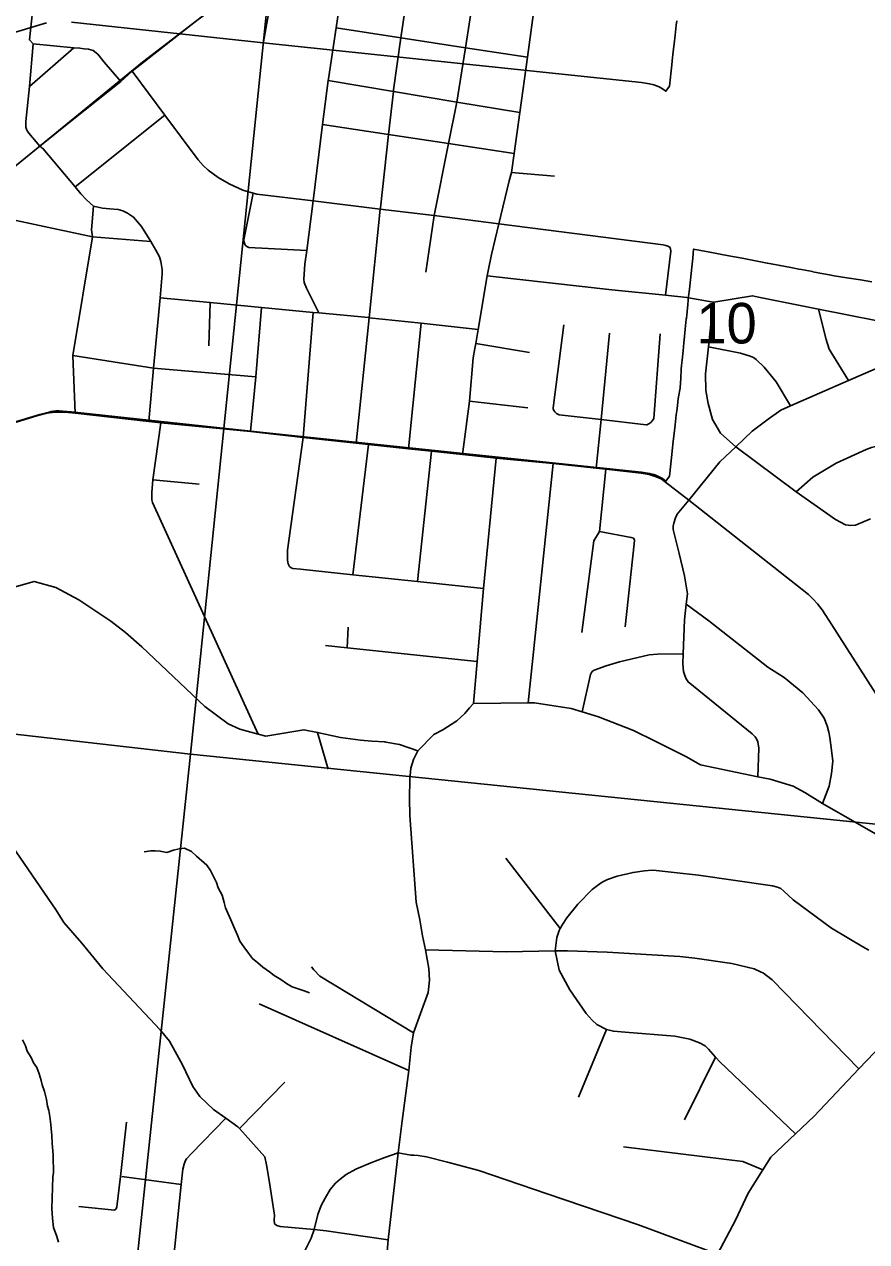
# Model space of a CAD drawing. Extents: x -8.2 to 38.5, y -0.1 to 21.9.
# Drawn here: x 7.706 to 8.576, y 17.376 to 18.635 of the extents above; entities that cross this region are included whole.
import ezdxf

# ---------------------------------------------------------------- set-up
doc = ezdxf.new("R2010")
doc.units = 0
for name, color, linetype in [('Default', 7, 'Continuous'), ('GM_X_Adjacent_County_Text', 7, 'Continuous'), ('GM_X_Airport_Location_Class_3', 7, 'Continuous'), ('GM_X_County_Road_Text', 7, 'Continuous'), ('GM_X_Minor_River', 7, 'Continuous'), ('GM_X_Section_Text', 7, 'Continuous'), ('GM_X_Township_Subdivision_Text', 7, 'Continuous'), ('GM_X_Township_Text', 7, 'Continuous'), ('GM_X_US_Location', 7, 'Continuous')]:
    doc.layers.add(name, color=color, linetype=linetype)

msp = doc.modelspace()

# ---------------------------------------------------------------- linework, layer by layer
at = {"layer": 'Default'}
msp.add_lwpolyline([(8.9634, 18.556), (8.9634, 18.7145), (7.9789, 18.8702), (7.8777, 17.8803), (8.8823, 17.7777)], close=True, dxfattribs=at)
for points in [[(7.7289, 18.6361), (7.722, 18.6342), (7.629, 18.6062), (7.6, 18.5978), (7.5969, 18.5969), (7.5925, 18.5959), (7.5878, 18.5953), (7.5775, 18.5947), (7.5814, 18.6069), (7.6487, 18.8063)], [(8.3802, 18.6382), (8.3797, 18.6339), (8.3786, 18.6236), (8.3775, 18.6145), (8.3762, 18.6038), (8.3762, 18.603), (8.3758, 18.6002), (8.375, 18.5929), (8.3725, 18.5707), (8.369, 18.5654), (8.3653, 18.568), (8.3618, 18.5699), (8.3591, 18.5711), (8.3563, 18.5721), (8.3521, 18.5733), (8.3477, 18.5739), (8.3436, 18.5744), (7.9594, 18.6149), (7.7548, 18.6369)]]:
    msp.add_lwpolyline(points, dxfattribs=at)
at = {"layer": 'GM_X_Adjacent_County_Text'}
for points in [[(6.9585, 18.9896), (7.9789, 18.8702), (7.8777, 17.8803), (6.8589, 17.9964)], [(6.8589, 17.9964), (7.8777, 17.8803), (7.7722, 16.8835), (6.7536, 16.9855)], [(7.8777, 17.8803), (8.8823, 17.7777), (8.7794, 16.8117), (7.7722, 16.8835)]]:
    msp.add_lwpolyline(points, close=True, dxfattribs=at)
at = {"layer": 'GM_X_Airport_Location_Class_3'}
msp.add_lwpolyline([(8.4223, 17.3635), (8.441, 17.3986), (8.4539, 17.4264), (8.4691, 17.4508), (8.4773, 17.4639), (8.5028, 17.4879), (8.522, 17.506), (8.5683, 17.5551), (8.5844, 17.5721), (8.6351, 17.6259), (8.6429, 17.6341), (8.7111, 17.7045), (8.7547, 17.7501), (8.8431, 17.8388), (8.8435, 17.8393), (8.8783, 17.8753), (8.8884, 17.8837), (8.8984, 17.8911)], dxfattribs=at)
at = {"layer": 'GM_X_Minor_River'}
for points in [[(7.8299, 17.7794), (7.8368, 17.7803), (7.8413, 17.7805), (7.8462, 17.7799), (7.8534, 17.7788), (7.8603, 17.7812), (7.8661, 17.7825), (7.8714, 17.783), (7.8789, 17.7797), (7.884, 17.7749), (7.8947, 17.7657), (7.8983, 17.7599), (7.9015, 17.754), (7.9046, 17.7478), (7.9063, 17.742), (7.9106, 17.7346), (7.9126, 17.727), (7.9139, 17.7216), (7.9195, 17.7092), (7.9236, 17.6995), (7.9264, 17.6933), (7.9288, 17.6871), (7.9328, 17.6813), (7.9375, 17.6746), (7.9418, 17.6691), (7.9473, 17.6647), (7.9525, 17.6603), (7.9595, 17.6554), (7.9643, 17.6514), (7.971, 17.6474), (7.9769, 17.6433), (7.9828, 17.64), (7.9888, 17.6379), (7.9952, 17.6357), (8.0005, 17.6336)], [(7.704, 17.585), (7.7072, 17.5788), (7.709, 17.5734), (7.713, 17.5668), (7.7155, 17.5614), (7.7188, 17.5564), (7.7213, 17.5498), (7.7234, 17.5429), (7.7244, 17.5387), (7.7269, 17.5318), (7.7289, 17.5234), (7.7299, 17.5165), (7.7313, 17.5119), (7.7322, 17.5057), (7.7335, 17.4977), (7.7338, 17.4935), (7.7344, 17.4863), (7.7349, 17.4779), (7.7354, 17.4702), (7.7357, 17.466), (7.7359, 17.4592), (7.7361, 17.4531), (7.736, 17.4481), (7.7355, 17.4436), (7.7346, 17.4105), (7.7348, 17.4059), (7.7351, 17.4009), (7.7363, 17.391), (7.7395, 17.3818), (7.7413, 17.376)]]:
    msp.add_lwpolyline(points, dxfattribs=at)
at = {"layer": 'GM_X_Section_Text'}
msp.add_lwpolyline([(8.5816, 18.3685), (8.5701, 18.3704), (8.5558, 18.3727), (8.5428, 18.3748), (8.5378, 18.3756), (8.5316, 18.3768), (8.5206, 18.3789), (8.5204, 18.379), (8.5092, 18.3811), (8.5064, 18.3816), (8.4999, 18.3829), (8.4981, 18.3832), (8.4869, 18.3853), (8.4739, 18.3878), (8.4737, 18.3879), (8.4599, 18.3905), (8.4478, 18.3928), (8.4339, 18.3955), (8.4144, 18.3992), (8.4051, 18.4009), (8.3976, 18.4024), (8.3966, 18.393), (8.3956, 18.3836), (8.3932, 18.361), (8.3924, 18.3534), (8.3916, 18.3452), (8.3904, 18.3339), (8.3901, 18.3309), (8.39, 18.3298), (8.389, 18.3197), (8.3878, 18.3085), (8.3875, 18.3056), (8.3866, 18.2971), (8.3856, 18.2876), (8.3851, 18.2821), (8.3848, 18.2782), (8.3842, 18.2686), (8.3836, 18.2593), (8.3835, 18.2586), (8.3821, 18.2498), (8.3813, 18.2447), (8.3808, 18.2404), (8.3802, 18.2353), (8.3797, 18.231), (8.3786, 18.2208), (8.3775, 18.2116), (8.3762, 18.2009), (8.3762, 18.2001), (8.3758, 18.1973), (8.375, 18.19), (8.3725, 18.1678), (8.369, 18.1625), (8.3653, 18.1651), (8.3618, 18.1671), (8.3591, 18.1683), (8.3563, 18.1693), (8.3521, 18.1704), (8.3477, 18.1711), (8.3436, 18.1716), (7.9594, 18.212), (7.7548, 18.234), (7.7458, 18.2349), (7.7421, 18.2351), (7.7404, 18.2351), (7.7385, 18.235), (7.736, 18.2347), (7.7339, 18.2344), (7.7316, 18.2338), (7.7289, 18.2332), (7.722, 18.2313), (7.629, 18.2033)], dxfattribs=at)
at = {"layer": 'GM_X_Township_Subdivision_Text'}
for p, q in [((7.953, 18.6164), (7.9662, 18.691)), ((7.7112, 18.5703), (7.7571, 18.6103)), ((7.7585, 18.4666), (7.8512, 18.5409)), ((8.2094, 18.4816), (8.2539, 18.4776)), ((8.121, 18.3785), (8.1294, 18.4369)), ((7.8966, 18.3022), (7.8982, 18.347)), ((7.9942, 18.2076), (8.0045, 18.3369)), ((8.103, 18.1959), (8.1159, 18.3257)), ((8.1725, 18.3049), (8.228, 18.2953)), ((8.166, 18.2452), (8.2261, 18.2383)), ((8.0455, 18.0658), (8.0616, 18.2005)), ((8.1121, 18.0587), (8.1268, 18.1935)), ((8.2267, 17.9333), (8.2526, 18.1806)), ((7.8388, 18.1639), (7.8868, 18.1594)), ((8.0396, 17.9903), (8.0405, 18.0115)), ((8.0201, 17.8648), (8.0091, 17.9027)), ((8.2598, 17.7001), (8.2036, 17.7729)), ((7.9486, 17.6221), (8.1033, 17.5533)), ((8.2785, 17.5259), (8.3074, 17.5956)), ((8.3882, 17.5025), (8.4202, 17.567)), ((7.9283, 17.4934), (7.9752, 17.5412)), ((7.8068, 17.4437), (7.8682, 17.4355))]:
    msp.add_line(p, q, dxfattribs=at)
for points in [[(8.0104, 18.3364), (7.9976, 18.3618), (7.9953, 18.3678), (7.9948, 18.3714), (7.996, 18.3866), (7.9978, 18.401), (8.0043, 18.4521), (8.0142, 18.531), (8.02, 18.5765), (8.0202, 18.5784), (8.0281, 18.6309), (8.0367, 18.6901), (8.0452, 18.7465), (8.054, 18.8028), (8.0623, 18.859), (8.0642, 18.8692), (8.0663, 18.8751), (8.0706, 18.8809), (8.102, 18.91)], [(8.0489, 18.2017), (8.0624, 18.3314), (8.0737, 18.4436), (8.0739, 18.4449), (8.0823, 18.5207), (8.0873, 18.5653), (8.0874, 18.567), (8.0952, 18.6207), (8.1036, 18.6788), (8.1119, 18.7365), (8.1197, 18.7914), (8.1284, 18.8486)], [(8.1294, 18.4369), (8.1443, 18.5113), (8.1529, 18.5543), (8.1617, 18.6105), (8.1707, 18.6686), (8.1795, 18.7252), (8.188, 18.7796), (8.1923, 18.8072), (8.1942, 18.8382)], [(8.1589, 18.19), (8.166, 18.2452), (8.1698, 18.2901), (8.1716, 18.2995), (8.1725, 18.3049), (8.1749, 18.3193), (8.1843, 18.3748), (8.1852, 18.3798), (8.1887, 18.3968), (8.1963, 18.4284), (8.2071, 18.4728), (8.2094, 18.4816), (8.212, 18.5011), (8.2179, 18.5435), (8.2259, 18.6006), (8.234, 18.6591), (8.2342, 18.6607), (8.242, 18.7148), (8.2497, 18.769), (8.2576, 18.8235)], [(7.7222, 18.5086), (7.7107, 18.522), (7.7085, 18.5251), (7.7077, 18.5284), (7.7076, 18.5318), (7.7077, 18.5341), (7.7112, 18.5703), (7.7153, 18.6144), (7.7113, 18.6186), (7.7146, 18.6474), (7.7191, 18.6732)], [(8.0281, 18.6309), (8.0952, 18.6207), (8.1617, 18.6105), (8.2259, 18.6006)], [(7.7153, 18.6144), (7.7571, 18.6103), (7.7632, 18.61), (7.7677, 18.6094), (7.7723, 18.6088), (7.7771, 18.6075), (7.782, 18.6037), (7.7886, 18.5954), (7.8057, 18.5756)], [(7.8176, 18.5863), (7.8512, 18.5409), (7.8855, 18.4946), (7.8907, 18.4887), (7.8961, 18.4838), (7.9063, 18.4762), (7.9175, 18.4698), (7.9317, 18.4633), (7.9423, 18.4602), (7.9464, 18.4591), (8.0043, 18.4521), (8.0737, 18.4436), (8.1294, 18.4369), (8.1963, 18.4284), (8.3661, 18.4067), (8.3689, 18.4062), (8.371, 18.4055)], [(8.02, 18.5765), (8.0873, 18.5653), (8.1529, 18.5543), (8.2179, 18.5435)], [(8.0142, 18.531), (8.0823, 18.5207), (8.1443, 18.5113), (8.1555, 18.5096)], [(7.8345, 18.2242), (7.8396, 18.2791), (7.8464, 18.3519), (7.8486, 18.3766), (7.8485, 18.3811), (7.8476, 18.3854), (7.8469, 18.3895), (7.8456, 18.3942), (7.8437, 18.3981), (7.842, 18.4011), (7.8366, 18.4102), (7.8271, 18.4256), (7.8189, 18.4355), (7.8125, 18.4396), (7.8079, 18.442), (7.8031, 18.4434), (7.7944, 18.4439), (7.7868, 18.4445), (7.7774, 18.4468), (7.7702, 18.4531), (7.7644, 18.4593), (7.7585, 18.4666), (7.7256, 18.506), (7.7222, 18.5086)], [(8.1555, 18.5096), (8.16, 18.509), (8.212, 18.5011)], [(7.9343, 18.4065), (7.9333, 18.4094), (7.9329, 18.4111), (7.9329, 18.412), (7.9423, 18.4602)], [(7.7587, 18.2326), (7.7562, 18.2924), (7.7763, 18.4151), (7.7753, 18.4223), (7.7774, 18.4468)], [(7.6619, 18.4396), (7.7763, 18.4151), (7.8366, 18.4102)], [(7.9343, 18.4065), (7.9358, 18.4051), (7.9367, 18.4045), (7.9381, 18.4041), (7.9978, 18.401)], [(8.3684, 18.3546), (8.3739, 18.4003), (8.3738, 18.4026), (8.3735, 18.4033), (8.3729, 18.4042), (8.371, 18.4055)], [(8.1843, 18.3748), (8.3129, 18.3603), (8.3684, 18.3546), (8.3905, 18.3523)], [(7.8464, 18.3519), (7.8982, 18.347), (7.9512, 18.342), (8.0045, 18.3369), (8.0104, 18.3364), (8.0617, 18.3315), (8.0624, 18.3314), (8.1159, 18.3257), (8.1749, 18.3193)], [(8.3905, 18.3523), (8.4176, 18.3476), (8.4185, 18.3474), (8.4585, 18.3541), (8.4645, 18.3528), (8.5267, 18.3403), (8.6171, 18.3222), (8.6193, 18.3215), (8.6209, 18.3206), (8.6218, 18.3191), (8.6227, 18.316), (8.6249, 18.2957), (8.6207, 18.2723)], [(8.5802, 18.1236), (8.5649, 18.1171), (8.5601, 18.1165), (8.5546, 18.1174), (8.5441, 18.123), (8.5034, 18.1513), (8.4412, 18.198), (8.4252, 18.2122), (8.4171, 18.2261), (8.4126, 18.2429), (8.4102, 18.2563), (8.4099, 18.2734), (8.4128, 18.3012), (8.4176, 18.3476)], [(7.9396, 18.2137), (7.9453, 18.2704), (7.9512, 18.342)], [(8.5577, 18.2664), (8.5376, 18.2989), (8.5345, 18.3089), (8.5267, 18.3403)], [(8.254, 18.2341), (8.253, 18.2354), (8.2523, 18.2374), (8.2523, 18.2382), (8.2633, 18.324)], [(8.297, 18.1759), (8.3019, 18.2262), (8.3105, 18.3155)], [(8.3532, 18.223), (8.3552, 18.2252), (8.3563, 18.2274), (8.3629, 18.3148)], [(8.4128, 18.3012), (8.4461, 18.2946), (8.4559, 18.2917), (8.4595, 18.2902), (8.4622, 18.2882), (8.4704, 18.2804), (8.483, 18.2652), (8.4978, 18.2403)], [(7.7562, 18.2924), (7.8396, 18.2791), (7.9453, 18.2704)], [(8.464, 17.857), (8.465, 17.8866), (8.464, 17.8931), (8.4627, 17.8961), (8.4612, 17.8983), (8.4581, 17.9012), (8.3918, 17.9549), (8.3897, 17.9581), (8.3885, 17.9615), (8.3872, 17.9658), (8.3865, 17.9737), (8.3869, 17.9839), (8.388, 18.0193), (8.39, 18.0352), (8.3913, 18.0459), (8.3883, 18.0646), (8.3828, 18.0876), (8.3765, 18.1125), (8.3765, 18.1159), (8.377, 18.1189), (8.3788, 18.1244), (8.3807, 18.1283), (8.3925, 18.143), (8.4248, 18.1825), (8.4412, 18.198), (8.4582, 18.214), (8.4745, 18.2266), (8.4876, 18.2358), (8.4978, 18.2403), (8.5577, 18.2664), (8.5854, 18.2784)], [(8.254, 18.2341), (8.2559, 18.2323), (8.2578, 18.2313), (8.2586, 18.2311), (8.3019, 18.2262), (8.3484, 18.2208), (8.3493, 18.2208), (8.3513, 18.2216), (8.3532, 18.223)], [(7.9475, 17.9011), (7.8386, 18.1404), (7.8379, 18.1431), (7.8376, 18.146), (7.8376, 18.1469), (7.8377, 18.1507), (7.8388, 18.1639), (7.847, 18.2226)], [(7.9787, 18.0769), (7.9781, 18.0807), (7.9778, 18.0849), (7.9778, 18.091), (7.9942, 18.2076)], [(8.5034, 18.1513), (8.5209, 18.1665), (8.5448, 18.1812), (8.5759, 18.1951), (8.5812, 18.1971), (8.5899, 18.1992), (8.5968, 18.1997), (8.6097, 18.1987), (8.6199, 18.1961), (8.6263, 18.1929), (8.6297, 18.1897), (8.6329, 18.1856), (8.6366, 18.179), (8.6403, 18.1681), (8.6458, 18.1521)], [(8.2822, 18.0062), (8.2946, 18.1007), (8.3002, 18.1105), (8.3067, 18.1749)], [(8.3267, 18.012), (8.3363, 18.0978), (8.3364, 18.1016), (8.336, 18.1026), (8.3353, 18.1035), (8.333, 18.1043), (8.3002, 18.1105)], [(7.9787, 18.0769), (7.9801, 18.0744), (7.9817, 18.073), (7.9835, 18.0723), (7.9915, 18.0715), (8.0455, 18.0658), (8.1121, 18.0587), (8.1804, 18.0515)], [(8.5308, 17.8293), (8.5377, 17.8472), (8.54, 17.8602), (8.5413, 17.873), (8.5402, 17.8843), (8.5383, 17.8976), (8.5373, 17.903), (8.5356, 17.9097), (8.5323, 17.9174), (8.5266, 17.9262), (8.5103, 17.9437), (8.491, 17.9594), (8.4741, 17.9701), (8.4134, 18.018), (8.39, 18.0352)], [(8.0173, 17.9927), (8.0396, 17.9903), (8.1738, 17.976)], [(8.2825, 17.9242), (8.291, 17.9626), (8.2922, 17.9648), (8.2929, 17.9658), (8.2938, 17.9664), (8.2949, 17.9671), (8.3072, 17.9717), (8.3209, 17.9756), (8.3518, 17.9829), (8.3602, 17.9838), (8.3869, 17.9839)], [(7.6807, 17.8035), (7.7389, 17.7192), (7.7468, 17.7063), (7.7654, 17.6848), (7.7872, 17.6586), (7.8465, 17.5955), (7.8561, 17.5835), (7.8696, 17.5592), (7.8801, 17.5369), (7.885, 17.53), (7.8875, 17.5265), (7.9016, 17.5129), (7.9142, 17.504), (7.9267, 17.4952), (7.9283, 17.4934), (7.9545, 17.4641), (7.9562, 17.4557), (7.9589, 17.4397), (7.9644, 17.4039), (7.964, 17.3988), (7.9645, 17.395), (7.9668, 17.393), (7.9703, 17.3922), (8.0056, 17.3891), (8.0178, 17.3876), (8.082, 17.3784)], [(8.2546, 17.6769), (8.2564, 17.6907), (8.2588, 17.6982), (8.2598, 17.7001), (8.262, 17.7043), (8.2666, 17.7113), (8.2781, 17.7252), (8.2929, 17.7405), (8.2981, 17.7447), (8.3029, 17.7479), (8.3087, 17.7506), (8.3187, 17.7543), (8.3351, 17.7581), (8.3468, 17.7598), (8.3549, 17.7604), (8.3588, 17.7602), (8.3773, 17.7579), (8.4027, 17.7551), (8.4792, 17.7442), (8.4841, 17.743), (8.4876, 17.7415), (8.4908, 17.7386), (8.5005, 17.7297), (8.5401, 17.7006), (8.5724, 17.6812), (8.5787, 17.6777)], [(8.1207, 17.6779), (8.204, 17.676), (8.2546, 17.6769), (8.2671, 17.6772), (8.3081, 17.6755), (8.3833, 17.6711), (8.3987, 17.6696), (8.4371, 17.6638), (8.4601, 17.6583), (8.4667, 17.6554), (8.4697, 17.6539), (8.4727, 17.6517), (8.4788, 17.6469), (8.5683, 17.5551)], [(8.2546, 17.6769), (8.2587, 17.6572), (8.2696, 17.6368), (8.2865, 17.6121), (8.2927, 17.6055), (8.2976, 17.601), (8.3074, 17.5956), (8.3147, 17.5939), (8.3268, 17.5929), (8.378, 17.5887), (8.3935, 17.5857), (8.4037, 17.582), (8.4094, 17.5787), (8.4129, 17.5753), (8.4202, 17.567), (8.4245, 17.5622), (8.5028, 17.4879)], [(8.0026, 17.6604), (8.0052, 17.6573), (8.0115, 17.6507), (8.1082, 17.5923)], [(7.8449, 17.2096), (7.8682, 17.4355), (7.8698, 17.4515), (7.871, 17.4566), (7.8723, 17.4598), (7.8736, 17.4621), (7.8786, 17.4677), (7.9142, 17.504)], [(7.7624, 17.4128), (7.7991, 17.409), (7.8008, 17.4104), (7.8015, 17.4126), (7.8053, 17.4439), (7.8115, 17.5001)], [(8.0464, 17.1047), (8.0579, 17.1826), (8.0808, 17.3663), (8.082, 17.3784), (8.0923, 17.4683)], [(8.0923, 17.4683), (8.1053, 17.4659), (8.1085, 17.4658), (8.1131, 17.4654), (8.1216, 17.464), (8.1432, 17.4586), (8.1756, 17.4499), (8.2461, 17.426), (8.3407, 17.3939), (8.4223, 17.3635)], [(8.3252, 17.4743), (8.4484, 17.4593), (8.4691, 17.4508)]]:
    msp.add_lwpolyline(points, dxfattribs=at)
at = {"layer": 'GM_X_Township_Text'}
for points in [[(7.6449, 18.3925), (7.648, 18.4019), (7.6619, 18.4396), (7.6681, 18.4532), (7.6732, 18.4626), (7.6781, 18.4697), (7.6873, 18.4796), (7.6962, 18.4876), (7.7222, 18.5086), (7.7572, 18.5369), (7.8057, 18.5756), (7.8176, 18.5863), (7.883, 18.6375), (7.9302, 18.6726), (7.9515, 18.6883), (7.9521, 18.689)], [(7.5965, 18.1925), (7.7201, 18.2303), (7.7293, 18.2328), (7.7376, 18.2338), (7.7478, 18.2339), (7.7587, 18.2326), (7.8345, 18.2242), (7.847, 18.2226), (7.9396, 18.2137), (7.9942, 18.2076), (8.0489, 18.2017), (8.0616, 18.2005), (8.103, 18.1959), (8.1268, 18.1935), (8.1589, 18.19), (8.1936, 18.1864), (8.2526, 18.1806), (8.297, 18.1759), (8.3067, 18.1749), (8.3434, 18.1709), (8.3516, 18.1695), (8.358, 18.1673), (8.3639, 18.1649), (8.3925, 18.143)], [(8.17, 17.9328), (8.1738, 17.976), (8.1804, 18.0515), (8.1936, 18.1864)], [(8.3925, 18.143), (8.5161, 18.0452), (8.5212, 18.0404), (8.5255, 18.0356), (8.5303, 18.0294), (8.5342, 18.0235), (8.5405, 18.0141), (8.6046, 17.9138), (8.6082, 17.9079), (8.61, 17.904), (8.611, 17.9), (8.6118, 17.8926), (8.6072, 17.7856)], [(7.6955, 18.0529), (7.7161, 18.0588), (7.7386, 18.0525), (7.7622, 18.0397), (7.7953, 18.0179), (7.8106, 18.006), (7.8274, 17.9912), (7.8924, 17.9296), (7.9167, 17.9116), (7.9287, 17.906), (7.9475, 17.9011), (7.9555, 17.899), (7.9949, 17.9056), (8.0091, 17.9027), (8.0326, 17.8976), (8.0535, 17.8948), (8.065, 17.8938), (8.0786, 17.8929)], [(8.0786, 17.8929), (8.0794, 17.8928), (8.0938, 17.8904), (8.1125, 17.8839), (8.1291, 17.9006), (8.1386, 17.9054), (8.1529, 17.9149), (8.1613, 17.9222), (8.1661, 17.9281), (8.17, 17.9328)], [(8.17, 17.9328), (8.2267, 17.9333), (8.233, 17.9334), (8.2712, 17.9276), (8.2825, 17.9242), (8.2992, 17.919), (8.3353, 17.9049), (8.3578, 17.8938), (8.3894, 17.8779), (8.4048, 17.8692), (8.464, 17.857), (8.4766, 17.8544), (8.5003, 17.8474), (8.5124, 17.8407), (8.5308, 17.8293), (8.6072, 17.7856)], [(8.0923, 17.4683), (8.0964, 17.5013), (8.1033, 17.5533), (8.1058, 17.5776), (8.1082, 17.5923), (8.1155, 17.6122), (8.1233, 17.634), (8.1245, 17.6467), (8.124, 17.6588), (8.1207, 17.6779), (8.1176, 17.6925), (8.1146, 17.7092), (8.1109, 17.7275), (8.1043, 17.8168), (8.1039, 17.8344), (8.1044, 17.8545), (8.1055, 17.8657), (8.108, 17.8748), (8.1125, 17.8839)], [(7.995, 17.3655), (8.0023, 17.3799), (8.0056, 17.3891), (8.0094, 17.4045), (8.0127, 17.4139), (8.0168, 17.4214), (8.0221, 17.4303), (8.0275, 17.4369), (8.0324, 17.4412), (8.0387, 17.4459), (8.0487, 17.4515), (8.064, 17.4579), (8.0786, 17.4635), (8.0923, 17.4683)]]:
    msp.add_lwpolyline(points, dxfattribs=at)
at = {"layer": 'GM_X_US_Location'}
msp.add_lwpolyline([(8.0122, 19.0043), (7.984, 18.9134), (7.9581, 18.6956), (7.828, 18.5957), (7.6866, 18.4798), (7.6586, 18.4459), (7.5702, 18.188), (7.5371, 18.0763), (7.5359, 18.0382), (7.5297, 17.9547), (7.5174, 17.9141), (7.4819, 17.8466), (7.4512, 17.7655), (7.4217, 17.7115), (7.3837, 17.6537), (7.3542, 17.6243), (7.3088, 17.5972)], dxfattribs=at)

# ---------------------------------------------------------------- texts
at = {"layer": 'GM_X_County_Road_Text'}
msp.add_text('10', height=0.04186, rotation=0, dxfattribs=at).set_placement((8.4005, 18.3048))

doc.saveas('drawing.dxf')
